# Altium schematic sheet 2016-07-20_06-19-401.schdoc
size 181 x 111 mm; SheetNumber: 1; SheetTotal: 1
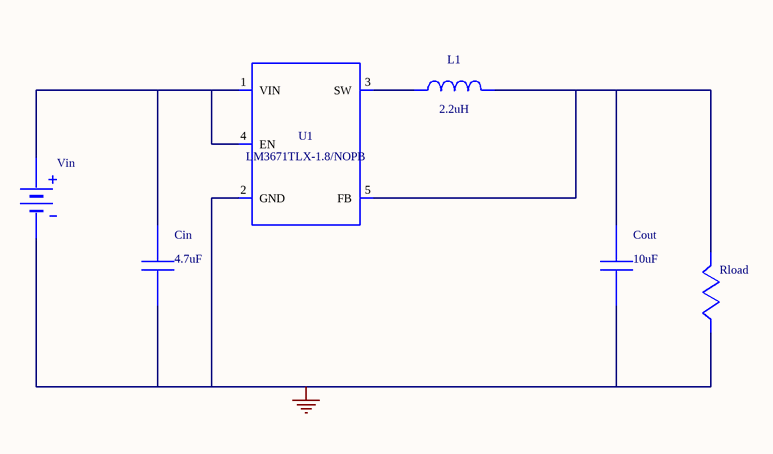
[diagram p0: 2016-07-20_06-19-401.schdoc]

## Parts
Cin  value 4.7uF  (hidden comment: GRM188R60J475KE19D)
Cout  value 10uF  (hidden comment: GRM188R60J106ME47D)
L1  value 2.2uH  (hidden comment: MLP2520S2R2MT0S1)
Rload  WB_LOAD_RESISTOR  (value not drawn)
U1  LM3671TLX-1.8/NOPB
Vin  WB_BATTERY  (value not drawn)

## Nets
0: Cin.2 Cout.2 Rload.2 U1.2(GND) Vin.2(-)
NetCin_1: Cin.1 U1.1(VIN) U1.4(EN) Vin.1(+)
NetCout_1: Cout.1 L1.2 Rload.1 U1.5(FB)
NetL1_1: L1.1 U1.3(SW)

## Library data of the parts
Cin = GRM188R60J475KE19D: GRM188R60J475KE1; Manufacturer Name: MuRata
Cout = GRM188R60J106ME47D: GRM188R60J106ME4; Manufacturer Name: MuRata
L1 = MLP2520S2R2MT0S1: Unknown; Manufacturer Name: TDK
U1 = LM3671TLX-1.8/NOPB: LM3671TLX-1.8/NO; Manufacturer Name: Texas Instruments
